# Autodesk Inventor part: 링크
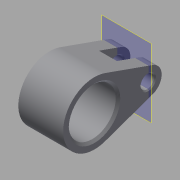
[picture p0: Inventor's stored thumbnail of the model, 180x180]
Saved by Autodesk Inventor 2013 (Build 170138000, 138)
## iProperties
Created: 2016-08
Part Number: 링크
Material: 강철, 탄소
Document SubType Name: Modeling
Designer: mduedu
Density: 7.87 g/cm^3
Author: mduedu
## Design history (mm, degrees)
sketch "스케치1"
  geometry: L1 (26, 5.657)-(4.667, 13.199); L2 (26, -5.657)-(4.667, -13.199); C1 r 10.5 at (0, 0); C2 r 3 at (24, 0); A1 r 14 centre (0, 0) between (4.667, 13.199) and (4.667, -13.199); A2 r 6 centre (24, 0) between (26, 5.657) and (26, -5.657); 1 further point
  constraints: 4 centre point, 4 end point, 4 point on circle, 4 tangent, 3 coincident, 1 horizontal alignment
  dimensions: "d0" = 28 diameter of A1; "d2" = 12 diameter of A2; "d3" = 24 distance of A2.centre point (0, 0); "d4" = 21 diameter of C1; "d5" = 6 diameter of C2
extrude "돌출1" new body sketch "스케치1" stored distance "d6" = 20; taper "d7" = 0 deg
sketch "스케치2"
  geometry: L1 (-10, 30)-(10, 30) reference; L2 (0, 0)-(0, 30); L3 (-4, 30)-(4, 30); L4 (4, 30)-(4, 16); L5 (4, 16)-(-4, 16); L6 (-4, 16)-(-4, 30)
  constraints: 10 end point, 2 midpoint, 2 parallel, 1 horizontal, 1 perpendicular, 1 point on line
  dimensions: "d8" = 8 distance between parallel lines of L4 L6; "d10" = 14 distance of L3.end L4.end
extrude "돌출2" cut sketch "스케치2" stored distance "d11" = 20; taper "d12" = 0 deg
chamfer "모따기1" distance "d13" = 1; stored, may be unused: second distance "d14" = 2, angle "d15" = 45 deg
chamfer "모따기2" distance "d16" = 0.5; stored, may be unused: second distance "d17" = 2, angle "d18" = 45 deg
node "작업 평면1"
node "솔리드1"
other parameters: "d19" = 24.25
